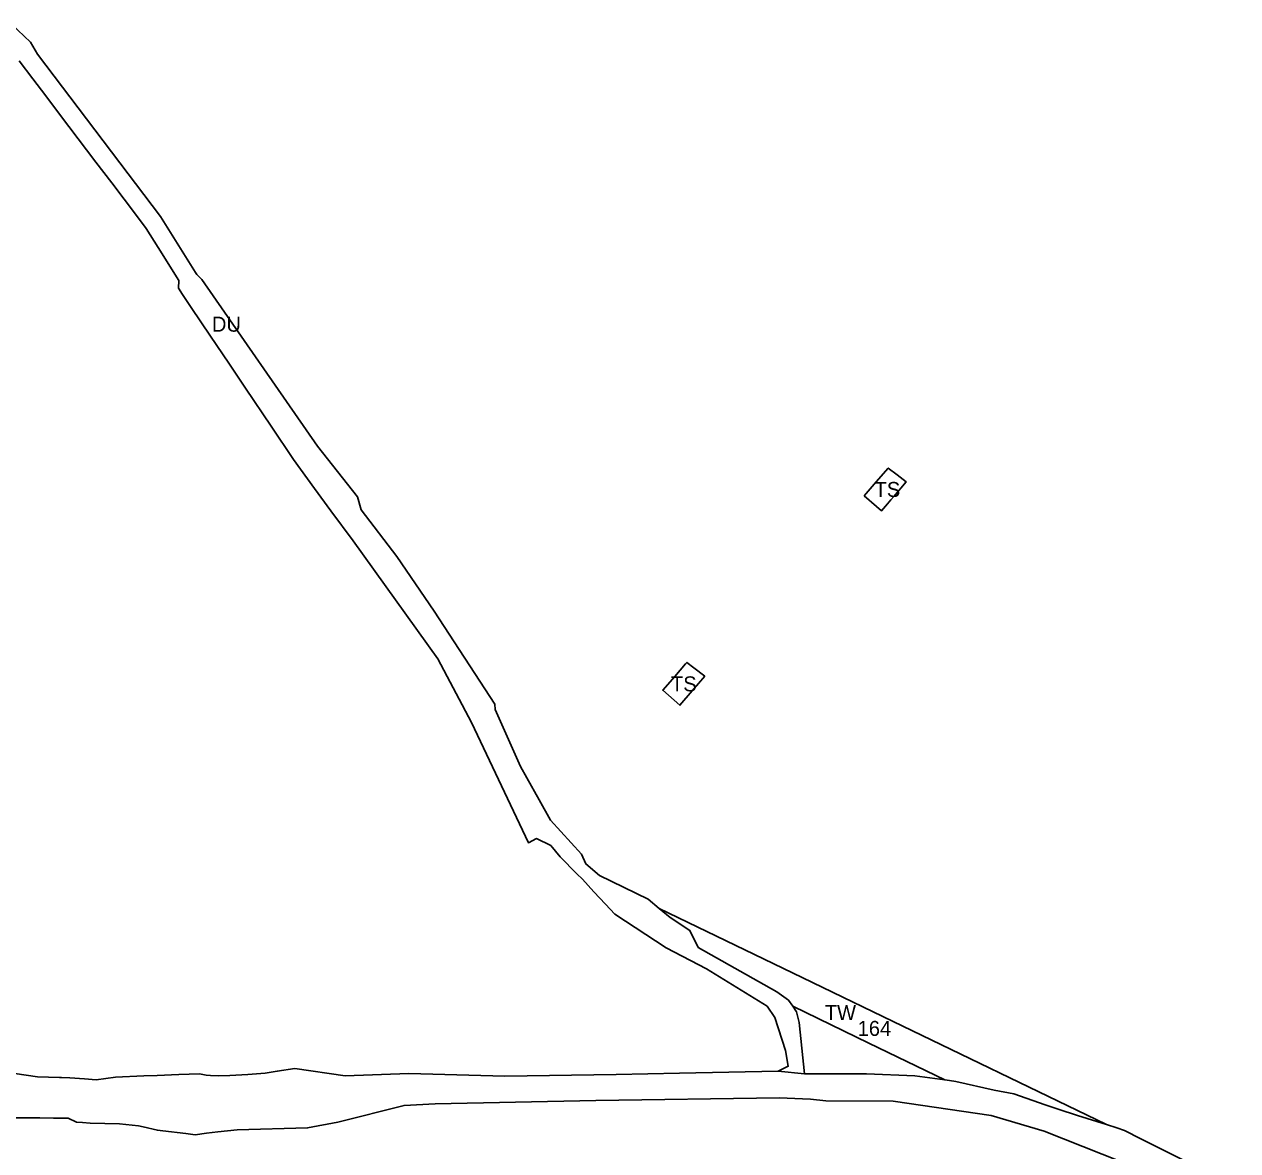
# Model space of a CAD drawing. Extents: x -521047 to -518054, y -1194945 to -1189555.
# Drawn here: x -519036 to -518226, y -1193041 to -1192289 of the extents above; entities that cross this region are included whole.
import ezdxf

# ---------------------------------------------------------------- set-up
doc = ezdxf.new("R2010")
doc.units = 0
for name, color, linetype in [('90310013', 7, 'Continuous'), ('90320013', 7, 'Continuous'), ('90390023', 7, 'Continuous'), ('90410013', 7, 'Continuous'), ('ID_navrh', 7, 'Continuous')]:
    doc.layers.add(name, color=color, linetype=linetype)

msp = doc.modelspace()

# ---------------------------------------------------------------- linework, layer by layer
at = {"layer": '90310013'}
for points in [[(-518700.34, -1192792.29), (-518704.53, -1192784.74), (-518721.46, -1192746.65), (-518721.68, -1192743.22), (-518762.17, -1192681.14), (-518787.22, -1192644.65), (-518810.91, -1192613.58), (-518813.27, -1192604.88), (-518840.07, -1192570.95), (-518917.29, -1192459.81), (-518920.67, -1192456.5), (-518921.58, -1192455.03), (-518944.8, -1192417.71), (-519026.95, -1192309.4), (-519031.55, -1192301.49), (-519044.36, -1192289.47)], [(-519039.22, -1192313.8), (-519030.1, -1192325.84), (-519021.5, -1192337.2), (-519012.83, -1192348.64), (-519005.96, -1192357.71), (-518988.01, -1192381.41), (-518977.44, -1192395.36), (-518960.98, -1192417.09), (-518954.47, -1192425.68), (-518946.37, -1192438.53), (-518932.56, -1192460.45), (-518932.84, -1192465.6), (-518930.23, -1192469.72), (-518924.38, -1192478.48), (-518911.42, -1192497.6), (-518899.32, -1192515.59), (-518888.04, -1192532.35), (-518871, -1192557.6), (-518856.13, -1192579.88), (-518842.04, -1192599.23), (-518831.07, -1192614.22), (-518816.35, -1192634.29), (-518759.71, -1192712.86), (-518737.24, -1192755.42), (-518699.31, -1192835.73), (-518693.82, -1192832.93), (-518684.41, -1192837.53), (-518678.07, -1192845.16), (-518667.06, -1192856.49), (-518663.19, -1192859.9), (-518655.74, -1192868.43), (-518647.77, -1192876.73), (-518641.65, -1192883.29), (-518607.43, -1192905.72), (-518580.39, -1192919.85), (-518539.85, -1192944.8), (-518534.83, -1192952.24), (-518527.68, -1192974.39), (-518525.88, -1192984.87), (-518532.67, -1192988.21), (-518515.05, -1192990), (-518518.64, -1192955.67), (-518520.44, -1192948.52), (-518522.92, -1192944.85), (-518525.77, -1192940.63), (-518533.4, -1192935.15), (-518586.01, -1192905.56), (-518591.47, -1192894.23), (-518604.74, -1192885.62), (-518611.95, -1192879.61), (-518619.45, -1192873.36), (-518651.89, -1192857.45), (-518660.97, -1192849.86), (-518663.98, -1192843.4), (-518684.56, -1192820.7), (-518692.09, -1192807.13), (-518700.34, -1192792.29)]]:
    msp.add_lwpolyline(points, dxfattribs=at)
at = {"layer": '90320013'}
for points in [[(-518225.89, -1193065.68), (-518278.49, -1193039.24), (-518290.64, -1193033.2), (-518301.5, -1193027.7), (-518306.65, -1193026.04), (-518313.55, -1193023.81), (-518313.58, -1193023.8), (-518332.79, -1193017.61), (-518345.74, -1193013.45), (-518354.48, -1193010.65), (-518375.31, -1193003.18), (-518388.43, -1193000.81), (-518414.09, -1192994.92), (-518421.26, -1192993.97), (-518421.27, -1192993.97), (-518441.46, -1192991.31), (-518473.62, -1192989.89), (-518515.05, -1192990), (-518532.67, -1192988.21), (-518598.55, -1192989.35), (-518640.83, -1192990.3), (-518715.07, -1192991.54), (-518779.05, -1192989.61), (-518821.67, -1192991.23), (-518855.17, -1192986.26), (-518866.91, -1192988.22), (-518875.1, -1192989.54), (-518886.48, -1192990.45), (-518898.64, -1192990.98), (-518905.82, -1192991.22), (-518911.52, -1192991.08), (-518914.36, -1192990.89), (-518918.87, -1192990), (-518932.53, -1192990.45), (-518947.06, -1192990.9), (-518955.94, -1192991.19), (-518974.8, -1192992.13), (-518987.7, -1192993.82), (-518995.54, -1192993.27), (-519005.4, -1192992.65), (-519011.01, -1192992.42), (-519012.24, -1192992.37), (-519026.96, -1192991.92), (-519042.16, -1192989.58)], [(-519046.96, -1193019.18), (-519025.46, -1193019.32), (-519016.37, -1193019.41), (-519008.43, -1193019.45), (-519006.51, -1193019.53), (-519000.94, -1193022.11), (-518996.85, -1193022.41), (-518991.81, -1193022.8), (-518972.24, -1193023.25), (-518959.64, -1193024.58), (-518956.41, -1193025.34), (-518946.89, -1193027.59), (-518943.36, -1193028), (-518927.91, -1193029.78), (-518921.63, -1193030.5), (-518914.19, -1193029.54), (-518906.5, -1193028.54), (-518893.72, -1193027.32), (-518846.7, -1193025.98), (-518826.54, -1193022.13), (-518782.28, -1193010.93), (-518761.5, -1193009.97), (-518654.27, -1193007.7), (-518531.81, -1193005.92), (-518516.38, -1193006.51), (-518511.04, -1193006.71), (-518500.8, -1193007.81), (-518455.87, -1193008.08), (-518390.51, -1193017.79), (-518355.07, -1193028.15), (-518290.52, -1193053.74)]]:
    msp.add_lwpolyline(points, dxfattribs=at)
at = {"layer": '90390023'}
msp.add_lwpolyline([(-518522.92, -1192944.85), (-518472.09, -1192969.41), (-518421.27, -1192993.97), (-518421.26, -1192993.97), (-518414.09, -1192994.92), (-518388.43, -1193000.81), (-518375.31, -1193003.18), (-518354.48, -1193010.65), (-518345.74, -1193013.45), (-518332.79, -1193017.61), (-518313.58, -1193023.8), (-518462.75, -1192951.72), (-518523.11, -1192922.54), (-518611.93, -1192879.62), (-518611.95, -1192879.61), (-518604.74, -1192885.62), (-518591.47, -1192894.23), (-518586.01, -1192905.56), (-518533.4, -1192935.15), (-518525.77, -1192940.63), (-518522.92, -1192944.85)], dxfattribs=at)
at = {"layer": '90410013'}
for points in [[(-518475.18, -1192604.13), (-518466.94, -1192611.39), (-518463.74, -1192614.21), (-518459.66, -1192609.45), (-518457.5, -1192606.94), (-518455.45, -1192604.56), (-518447.16, -1192594.9), (-518453.26, -1192590.18), (-518459.09, -1192585.66), (-518467.14, -1192594.9), (-518475.18, -1192604.13)], [(-518581.63, -1192724.62), (-518588.95, -1192718.96), (-518593.57, -1192715.39), (-518593.98, -1192715.86), (-518594.38, -1192716.32), (-518601.62, -1192724.63), (-518609.66, -1192733.86), (-518598.22, -1192743.93), (-518589.93, -1192734.28), (-518581.63, -1192724.62)]]:
    msp.add_lwpolyline(points, dxfattribs=at)

# ---------------------------------------------------------------- texts
at = {"layer": '90310013'}
msp.add_text('DU', height=10, rotation=360, dxfattribs=at).set_placement((-518910.5, -1192494.62))
at = {"layer": '90390023'}
msp.add_text('TW', height=10, rotation=360, dxfattribs=at).set_placement((-518501.47, -1192954.07))
at = {"layer": '90410013'}
for rotation, p in [(360, (-518468.25, -1192604.93)), (0, (-518604.11, -1192734.65))]:
    msp.add_text('TS', height=10, rotation=rotation, dxfattribs=at).set_placement(p)
at = {"layer": 'ID_navrh'}
msp.add_text('164', height=10, rotation=0, dxfattribs=at).set_placement((-518479.55, -1192964.57))

doc.saveas('drawing.dxf')
